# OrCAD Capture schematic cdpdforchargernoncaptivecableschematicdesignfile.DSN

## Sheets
1 2 History_Sheet: title: Revision History; rev: 1.6
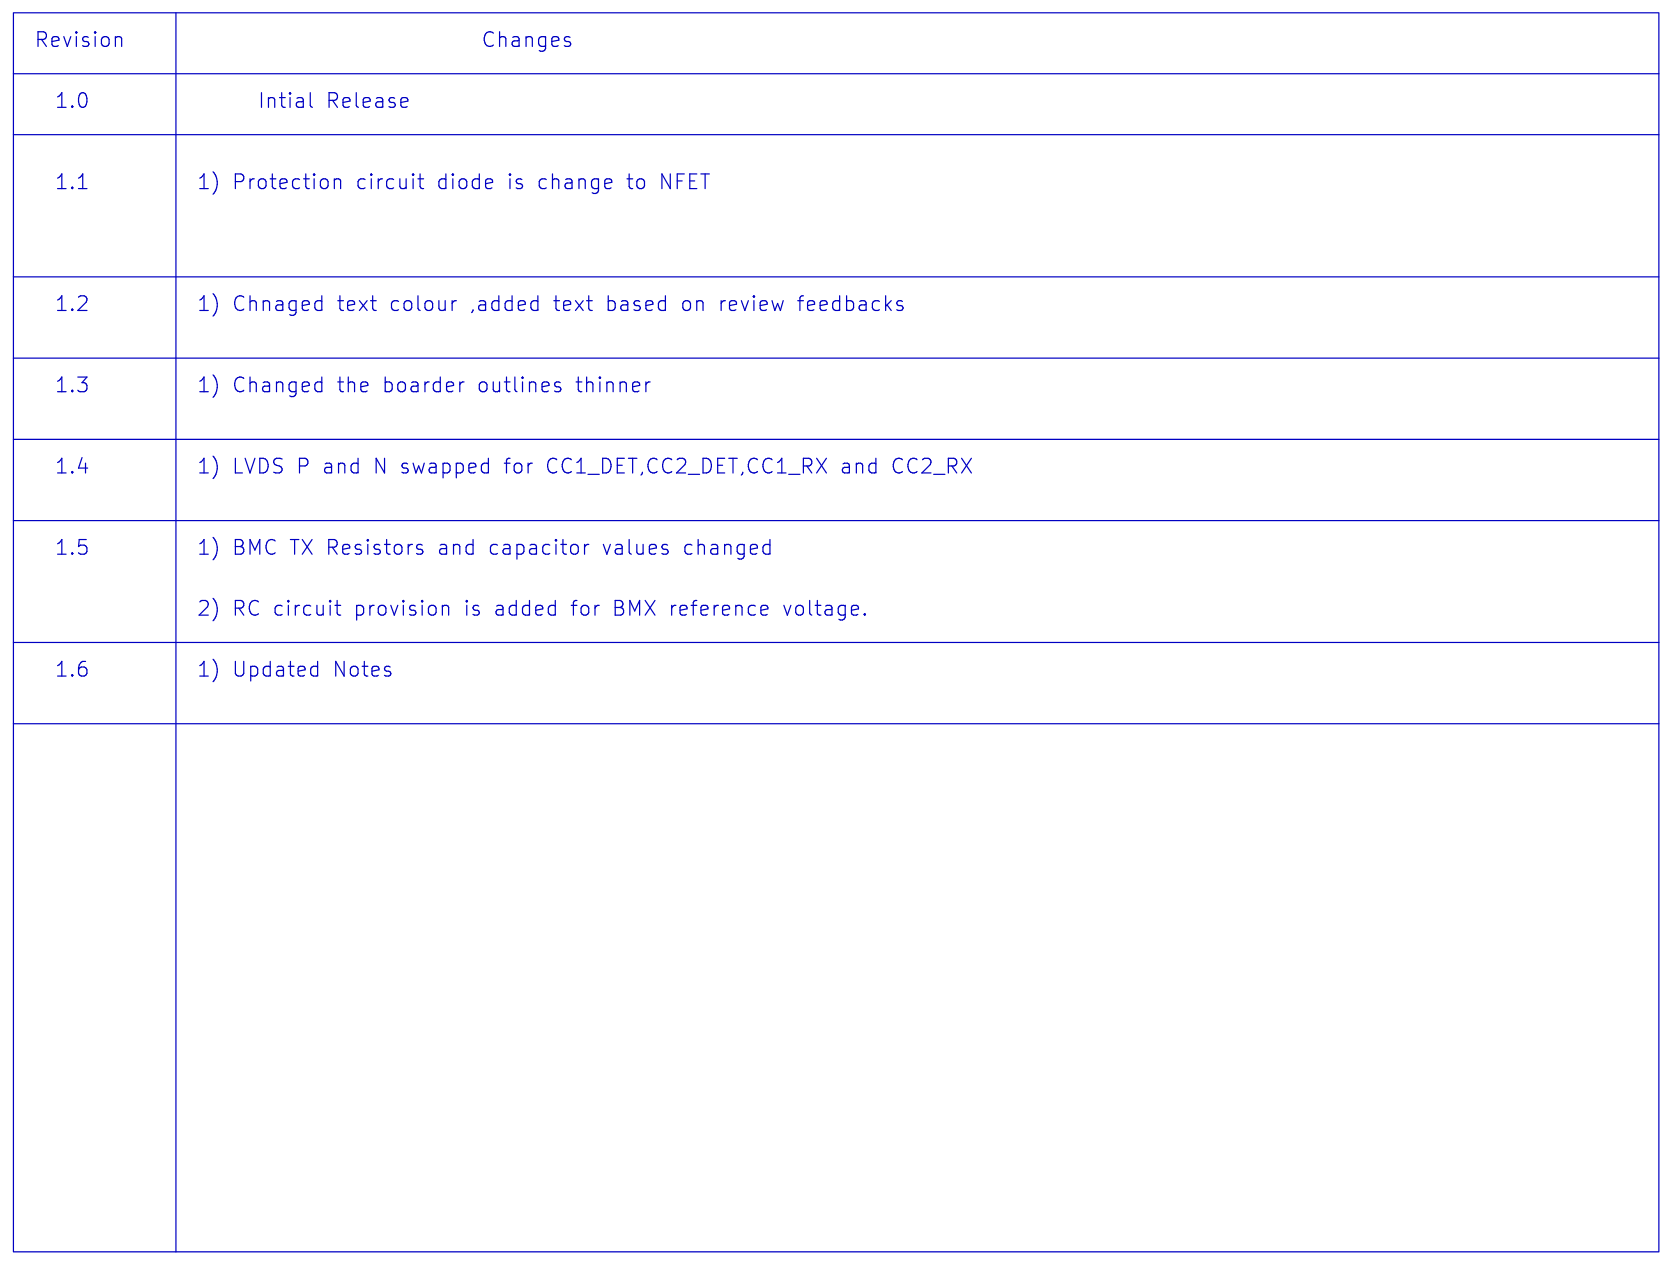
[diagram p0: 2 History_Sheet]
2 1 CD_PD_Charger_Non_Captive: size B; title: CD_PD_Charger_Non_Captive
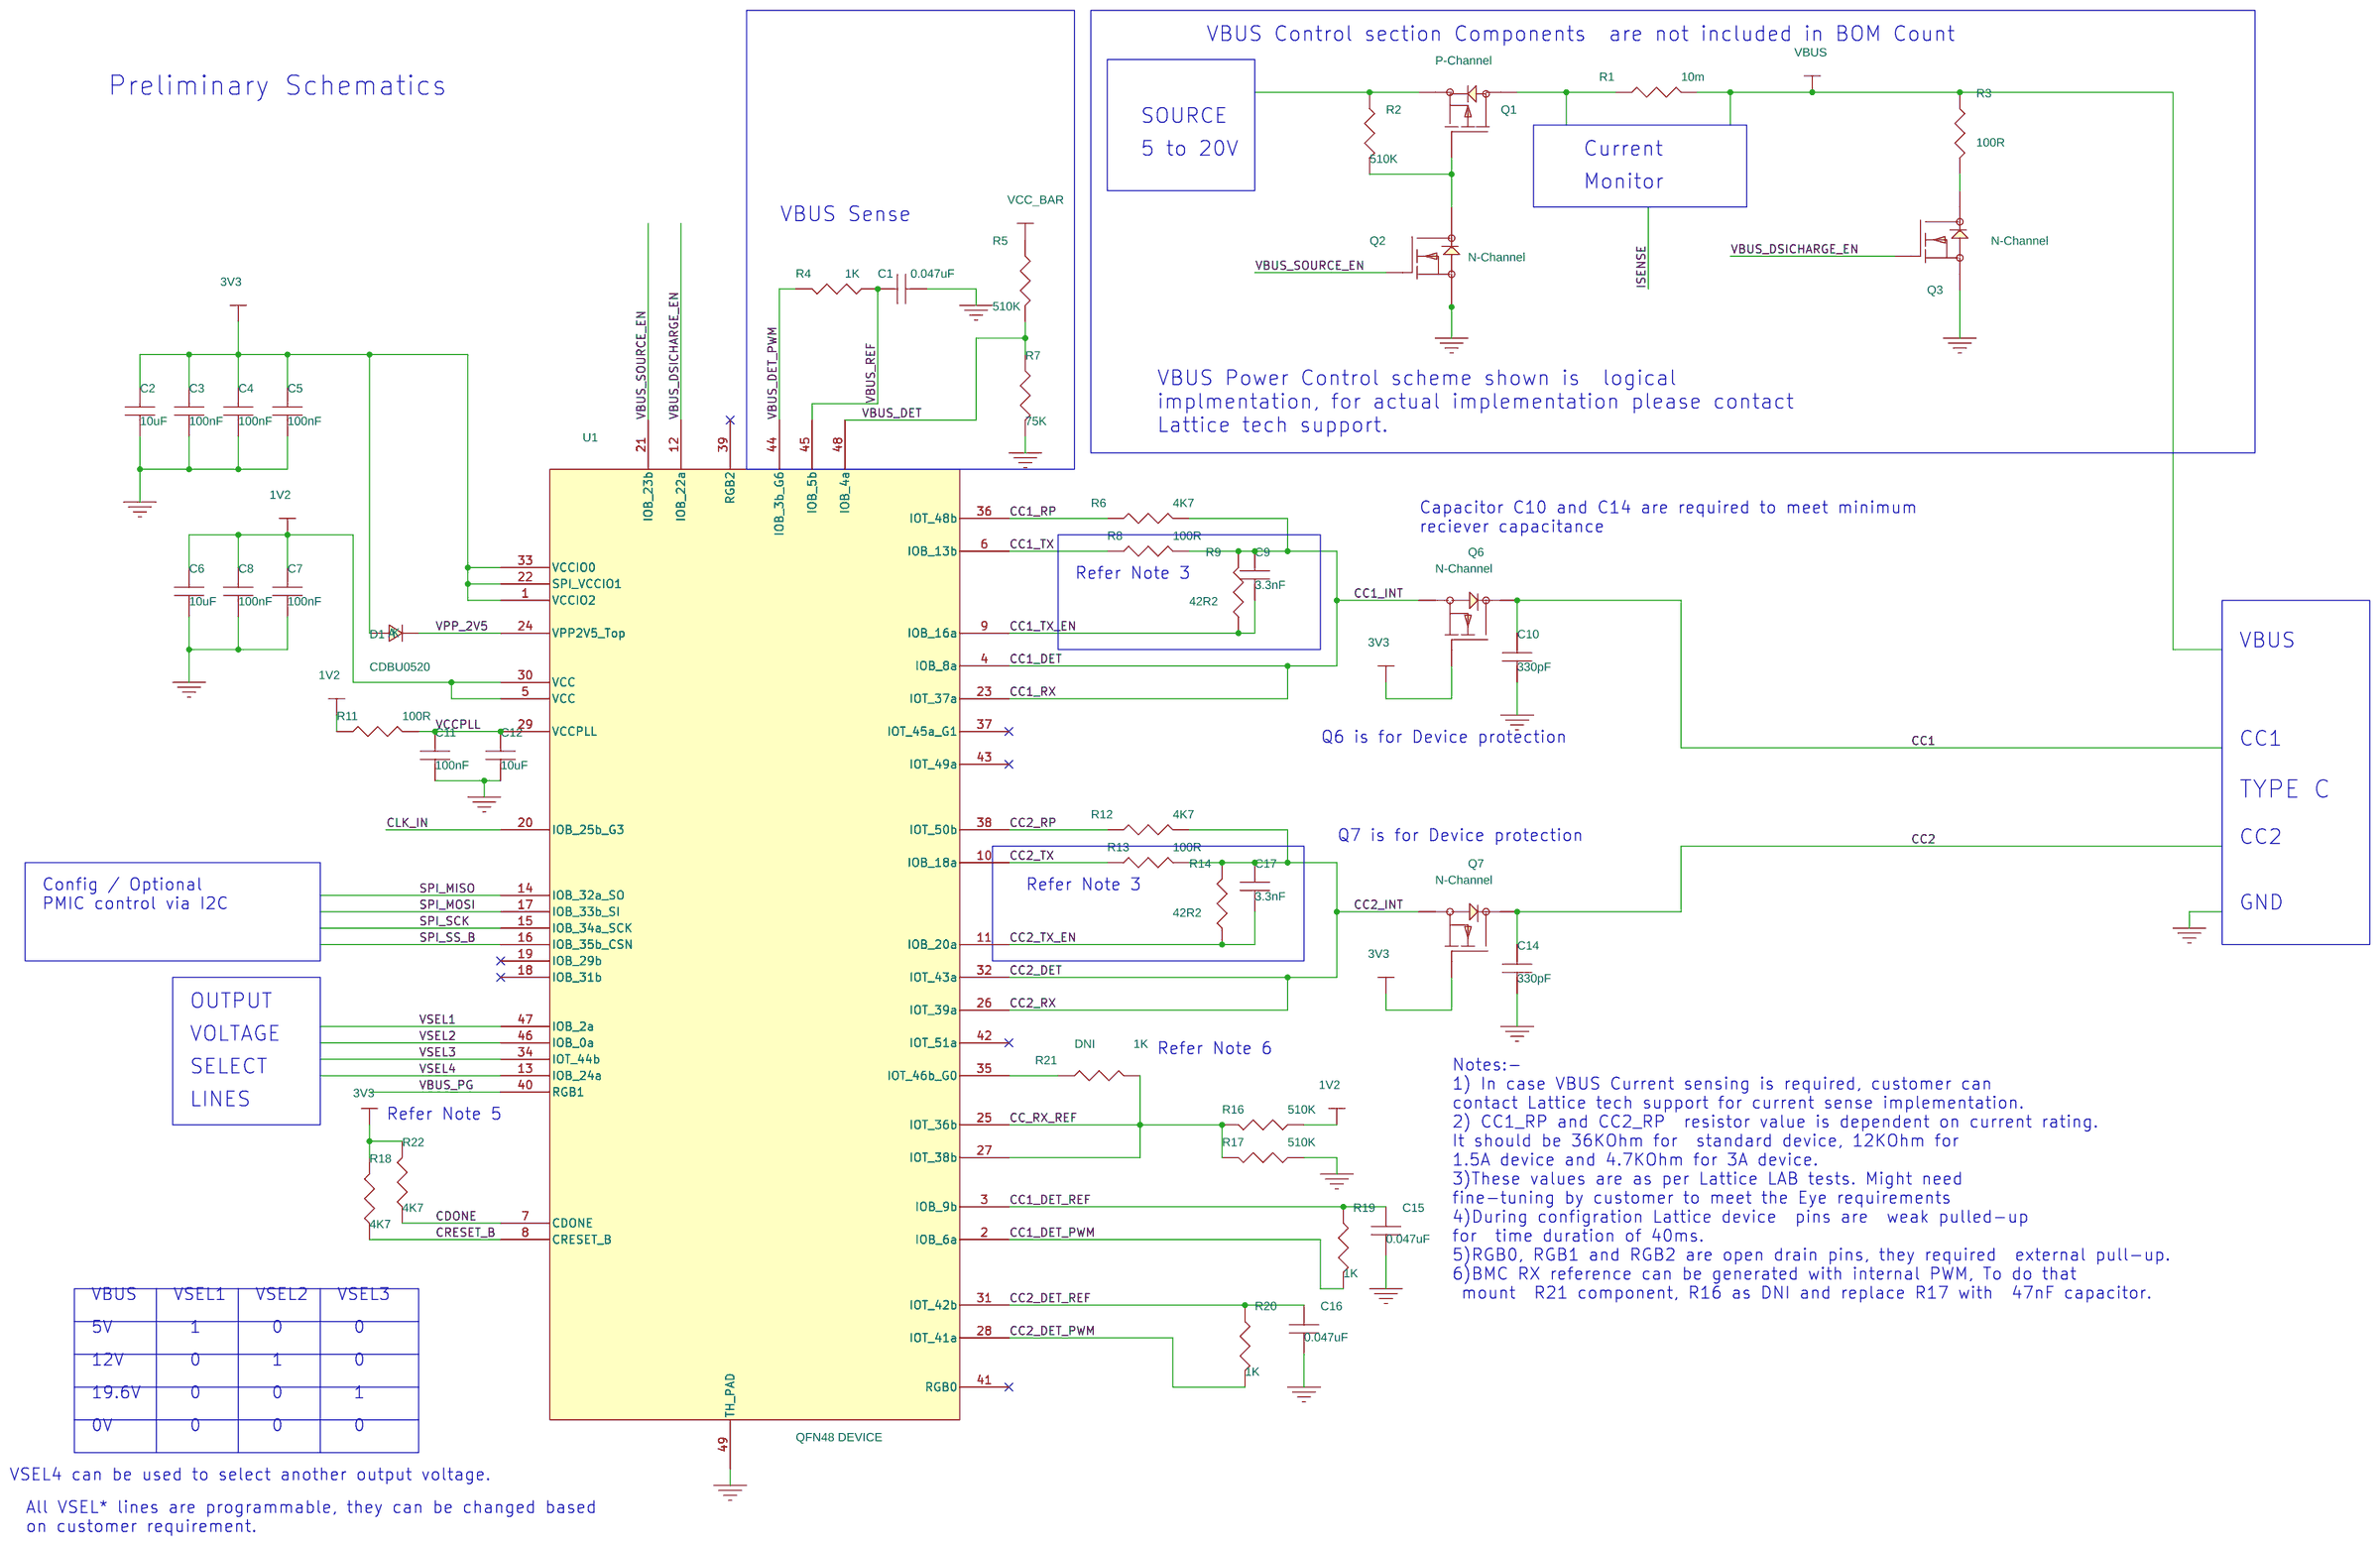
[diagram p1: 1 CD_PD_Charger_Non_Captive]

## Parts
C1  0.047uF  [C0402]
C2  10uF  [C0805]
C3  100nF  [C0402]
C4  100nF  [C0402]
C5  100nF  [C0402]
C6  10uF  [C0805]
C7  100nF  [C0402]
C8  100nF  [C0402]
C9  3.3nF  [C0402]
C10  330pF  [C0402]
C11  100nF  [C0402]
C12  10uF  [C0805]
C14  330pF  [C0402]
C15  0.047uF  [C0402]
C16  0.047uF  [C0402]
C17  3.3nF  [C0402]
D1  CDBU0520  [D0603]
Q1  P-Channel
Q2  N-Channel
Q3  N-Channel
Q6  N-Channel  [BSH103,235]
Q7  N-Channel  [BSH103,235]
R1  10m  [R1206]
R2  510K  [R0402]
R3  100R  [R0402]
R4  1K  [R0402]
R5  510K  [R0402]
R6  4K7  [R0402]
R7  75K  [R0402]
R8  100R  [R0402]
R9  42R2  [R0402]
R11  100R  [R0402]
R12  4K7  [R0402]
R13  100R  [R0402]
R14  42R2  [R0402]
R16  510K  [R0402]
R17  510K  [R0402]
R18  4K7  [R0402]
R19  1K  [R0402]
R20  1K  [R0402]
R21  1K  [R0402]
R22  4K7  [R0402]
U1  QFN48 DEVICE

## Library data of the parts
C1 C15 C16 = CAP_CER_0.047uF_0402_10V
C2 C6 C12 = CAP_CER_10uF_0805_10V
C3-C5 C7 C8 C11 = CAP_CER_100nF_0402_10V
C9 C17 = CAP_CER_3.3nF_0402_10V
C10 C14 = CAP_CER_330pF_0402_16V
D1 = DIODE_SCHOTTKY_20V_0603
Q1 = MOSFET_P-CHAN-1V_6A
Q2 = MOSFET_N-CHAN-0P45V_0P85A
Q3 = PWR_MOSFET-N-CH-0P9V_6P1A
Q6 Q7 = MOSFET_N-CHAN-0P45V_1
R1 = RES_10m_1W2_1206_1P
R2 R5 R16 R17 = RES_500K_1W16_0402_5P
R3 = RES_100R_1W_2512_1P
R4 R19 R20 = RES_1K_1W16_0402_5P
R6 R12 R18 R22 = RES_4K7_1W16_0402_5P
R7 = RES_75K_1W16_0402_5P
R8 R13 = RES_100R_1W16_0402_1P
R9 R14 = RES_42R_1W16_0402_1P
R11 = RES_100R_1W16_0402_5P
R21 = RES_1K_1W16_0402_5P: BOM_Note: DNI
U1 = iCE5LP4K__QFN48_New

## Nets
1V2: C6.1 C7.1 C8.1 R11.1 R16.1 U1.5(VCC) U1.30(VCC)
3V3: C2.1 C3.1 C4.1 C5.1 D1.1(A) Q6.1(G) Q7.1(G) R18.2 R22.2 U1.1(VCCIO2) U1.22(SPI_VCCIO1) U1.33(VCCIO0)
GND: C1.2 C2.2 C3.2 C4.2 C5.2 C6.2 C7.2 C8.2 C10.2 C11.2 C12.2 C14.2 C15.2 C16.2 Q2.2(S) Q3.2(S) R7.2 R17.1 U1.49(TH_PAD)
VBUS: R1.2 R3.1 R5.1
VBUS_DET: R5.2 R7.1 U1.48(IOB_4a)
VBUS_DET_PWM: R4.2 U1.44(IOB_3b_G6)
VBUS_DSICHARGE_EN: Q3.1(G) U1.12(IOB_22a)
VBUS_PG: U1.40(RGB1)
VBUS_REF: C1.1 R4.1 U1.45(IOB_5b)
VBUS_SOURCE_EN: Q2.1(G) U1.21(IOB_23b)
VCCPLL: C11.1 C12.1 R11.2 U1.29(VCCPLL)
CC1: C10.1 Q6.3(D)
CC1_DET: C9.1 Q6.2(S) R6.2 R8.2 R9.2 U1.4(IOB_8a) U1.23(IOT_37a)
CC1_DET_PWM: R19.2 U1.2(IOB_6a)
CC1_DET_REF: C15.1 R19.1 U1.3(IOB_9b)
CC1_RP: R6.1 U1.36(IOT_48b)
CC1_TX: R8.1 U1.6(IOB_13b)
CC1_TX_EN: C9.2 R9.1 U1.9(IOB_16a)
CC2: C14.1 Q7.3(D)
CC2_DET: C17.1 Q7.2(S) R12.2 R13.2 R14.2 U1.26(IOT_39a) U1.32(IOT_43a)
CC2_DET_PWM: R20.2 U1.28(IOT_41a)
CC2_DET_REF: C16.1 R20.1 U1.31(IOT_42b)
CC2_RP: R12.1 U1.38(IOT_50b)
CC2_TX: R13.1 U1.10(IOB_18a)
CC2_TX_EN: C17.2 R14.1 U1.11(IOB_20a)
CC_RX_REF: R16.2 R17.2 R21.2 U1.25(IOT_36b) U1.27(IOT_38b)
CDONE: R22.1 U1.7(CDONE)
CLK_IN: U1.20(IOB_25b_G3)
CRESET_B: R18.1 U1.8(CRESET_B)
SPI_MISO: U1.14(IOB_32a_SO)
SPI_MOSI: U1.17(IOB_33b_SI)
SPI_SCK: U1.15(IOB_34a_SCK)
SPI_SS_B: U1.16(IOB_35b_CSN)
VPP_2V5: D1.2(K) U1.24(VPP2V5_Top)
VSEL1: U1.47(IOB_2a)
VSEL2: U1.46(IOB_0a)
VSEL3: U1.34(IOT_44b)
VSEL4: U1.13(IOB_24a)
N16830420: Q1.2(S) R2.1
N16831330: Q1.1(G) Q2.3(D) R2.2
N16844099: Q1.3(D) R1.1
N16844170: Q3.3(D) R3.2
N16867608: R21.1 U1.35(IOT_46b_G0)

Not connected (* = marked no-connect by the designer): U1 18(IOB_31b)* 19(IOB_29b)* 37(IOT_45a_G1)* 39(RGB2)* 41(RGB0)* 42(IOT_51a)* 43(IOT_49a)*

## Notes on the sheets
sheet 1
- Revision
- Changes
- 1.0
- Intial Release
- 1.1
- 1) Protection circuit diode is change to NFET
- 1.2
- 1) Chnaged text colour ,added text based on review feedbacks
- 1.3
- 1) Changed the boarder outlines thinner
- 1.4
- 1) LVDS P and N swapped for CC1_DET,CC2_DET,CC1_RX and CC2_RX
- 1.5
- 1) BMC TX Resistors and capacitor values changed
- 2) RC circuit provision is added for BMX reference voltage.
- 1.6
- 1) Updated Notes
sheet 2
- VBUS Control section Components  are not included in BOM Count
- Preliminary Schematics
- SOURCE
- 5 to 20V
- Current
- Monitor
- VBUS Sense
- VBUS Power Control scheme shown is  logical
  implmentation, for actual implementation please contact
  Lattice tech support.
- Capacitor C10 and C14 are required to meet minimum
  reciever capacitance
- Refer Note 3
- VBUS
- Q6 is for Device protection
- CC1
- TYPE C
- Q7 is for Device protection
- CC2
- Config / Optional
  PMIC control via I2C
- Refer Note 3
- GND
- OUTPUT
- VOLTAGE
- Refer Note 6
- SELECT
- Notes:-
  1) In case VBUS Current sensing is required, customer can
  contact Lattice tech support for current sense implementation.
  2) CC1_RP and CC2_RP  resistor value is dependent on current rating.
  It should be 36KOhm for  standard device, 12KOhm for
  1.5A device and 4.7KOhm for 3A device.
  3)These values are as per Lattice LAB tests. Might need
  fine-tuning by customer to meet the Eye requirements
  4)During configration Lattice device  pins are  weak pulled-up
  for  time duration of 40ms.
  5)RGB0, RGB1 and RGB2 are open drain pins, they required  external pull-up.
  6)BMC RX reference can be generated with internal PWM, To do that
   mount  R21 component, R16 as DNI and replace R17 with  47nF capacitor.
- LINES
- Refer Note 5
- VBUS
- VSEL1
- VSEL2
- VSEL3
- 5V
- 1
- 0
- 0
- 12V
- 0
- 1
- 0
- 19.6V
- 0
- 0
- 1
- 0V
- 0
- 0
- 0
- VSEL4 can be used to select another output voltage.
- All VSEL* lines are programmable, they can be changed based
  on customer requirement.
